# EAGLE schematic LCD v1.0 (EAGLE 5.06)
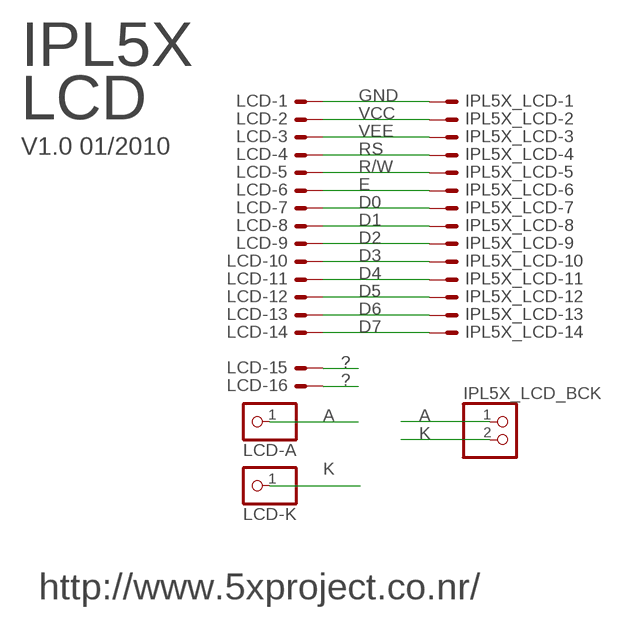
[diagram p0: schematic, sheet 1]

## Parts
IPL5X_LCD  ML14E  [ML14]
IPL5X_LCD_BCK  PINHD-1X2  [1X02]
LCD  ML16E  [ML16]
LCD-A  PINHD-1X1  [1X01]
LCD-K  PINHD-1X1  [1X01]

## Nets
?: LCD.15 LCD.16
A: IPL5X_LCD_BCK.1 LCD-A.1
D0: IPL5X_LCD.7 LCD.7
D1: IPL5X_LCD.8 LCD.8
D2: IPL5X_LCD.9 LCD.9
D3: IPL5X_LCD.10 LCD.10
D4: IPL5X_LCD.11 LCD.11
D5: IPL5X_LCD.12 LCD.12
D6: IPL5X_LCD.13 LCD.13
D7: IPL5X_LCD.14 LCD.14
E: IPL5X_LCD.6 LCD.6
GND: IPL5X_LCD.1 LCD.1
K: IPL5X_LCD_BCK.2 LCD-K.1
R/W: IPL5X_LCD.5 LCD.5
RS: IPL5X_LCD.4 LCD.4
VCC: IPL5X_LCD.2 LCD.2
VEE: IPL5X_LCD.3 LCD.3

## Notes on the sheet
- IPL5X
- LCD
- V1.0 01/2010
- http://www.5xproject.co.nr/

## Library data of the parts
IPL5X_LCD = con-harting-ml:ML14?E: HARTING
IPL5X_LCD_BCK = pinhead:PINHD-1X2: PIN HEADER
LCD = con-harting-ml:ML16?E: HARTING
LCD-A LCD-K = pinhead:PINHD-1X1: PIN HEADER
